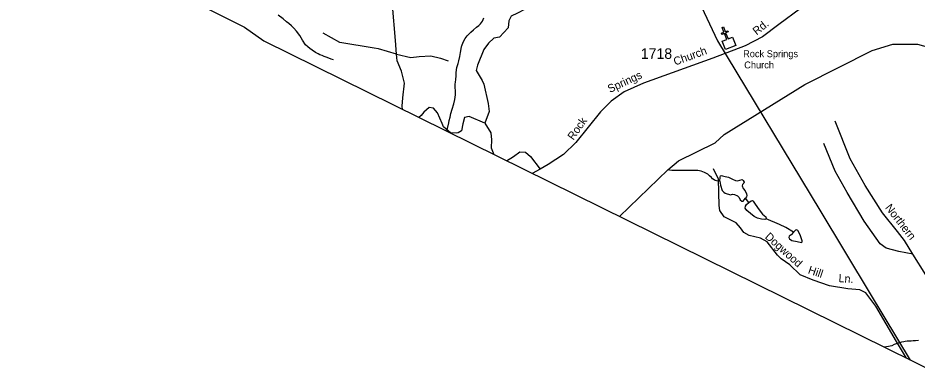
# Model space of a CAD drawing. Extents: x 2056842 to 2160602, y 826753 to 1016856.
# Drawn here: x 2099244 to 2109914, y 837921 to 842142 of the extents above; entities that cross this region are included whole.
import ezdxf

# ---------------------------------------------------------------- set-up
doc = ezdxf.new("R2010")
doc.units = 0
for name, color, linetype in [('Exist Boundary Political CountyLine', 7, 'Continuous'), ('Exist Cultural Church CELL', 7, 'Continuous'), ('Exist Cultural Church Label', 7, 'Continuous'), ('Exist Hydrographic Misc Water Feature', 7, 'Continuous'), ('Exist Road Non-System Type 51', 7, 'Continuous'), ('Exist Road Non-System Type 51 Label', 7, 'Continuous'), ('Exist Road Secondary Type 51 Attributed', 7, 'Continuous'), ('Exist Road Secondary Type 51 Label', 7, 'Continuous'), ('Exist Road Secondary Type 51 Number Label', 7, 'Continuous'), ('Exist Utilities Electrical Transmission Line', 7, 'Continuous')]:
    doc.layers.add(name, color=color, linetype=linetype)

msp = doc.modelspace()

# ---------------------------------------------------------------- linework, layer by layer
at = {"layer": 'Exist Boundary Political CountyLine'}
msp.add_lwpolyline([(2087202, 846842), (2088279, 846703), (2089061, 846621), (2089593, 846564), (2090401, 846476), (2091507, 846372), (2092417, 846284), (2093038, 846221), (2093614, 846163), (2094823, 845563), (2096040, 844956), (2096291, 844828), (2097736, 844110), (2098906, 843531), (2099955, 843015), (2100389, 842806), (2101933, 842033), (2102162, 841869), (2110170, 837921)], dxfattribs=at)
at = {"layer": 'Exist Cultural Church CELL'}
msp.add_lwpolyline([(2107603, 841867), (2107656, 841888), (2107628, 841959), (2107598, 841947), (2107593, 841962), (2107622, 841974), (2107601, 842030), (2107616, 842036), (2107637, 841980), (2107667, 841991), (2107673, 841976), (2107643, 841965), (2107671, 841894), (2107724, 841915), (2107763, 841815), (2107641, 841768)], close=True, dxfattribs=at)
at = {"layer": 'Exist Hydrographic Misc Water Feature'}
for points in [[(2102987, 841646), (2102963, 841654), (2102915, 841674), (2102879, 841686), (2102853, 841696), (2102827, 841706), (2102807, 841716), (2102777, 841734), (2102737, 841760), (2102709, 841781), (2102686, 841799), (2102656, 841825), (2102622, 841877), (2102590, 841933), (2102548, 841985), (2102518, 842021), (2102492, 842049), (2102458, 842078), (2102432, 842098), (2102390, 842130), (2102332, 842174)], [(2104333, 840799), (2104359, 840897), (2104363, 840928), (2104373, 840967), (2104381, 841009), (2104397, 841060), (2104415, 841125), (2104428, 841177), (2104436, 841231), (2104436, 841277), (2104434, 841319), (2104434, 841357), (2104438, 841379), (2104441, 841413), (2104445, 841455), (2104445, 841491), (2104447, 841529), (2104453, 841555), (2104467, 841601), (2104477, 841635), (2104487, 841685), (2104495, 841733), (2104502, 841777), (2104508, 841805), (2104511, 841813), (2104528, 841855), (2104550, 841897), (2104574, 841931), (2104618, 841973), (2104650, 842001), (2104686, 842032), (2104712, 842054), (2104734, 842074), (2104759, 842106), (2104773, 842144)], [(2106383, 839788), (2106958, 840341), (2107084, 840450), (2107517, 840661), (2107625, 840761), (2108581, 841355), (2109380, 841758), (2109629, 841832), (2109921, 841832), (2110305, 841726), (2110838, 841722), (2110920, 841729)], [(2107575, 840208), (2107533, 840213), (2107519, 840215), (2107505, 840222), (2107488, 840233), (2107473, 840250), (2107453, 840271), (2107433, 840289), (2107391, 840308), (2107352, 840324), (2107312, 840332), (2107248, 840334), (2107187, 840334), (2107156, 840334), (2107106, 840334), (2107004, 840335), (2106977, 840339), (2106958, 840341)], [(2107575, 840208), (2107576, 840254), (2107583, 840269), (2107595, 840274), (2107604, 840272), (2107636, 840264), (2107675, 840255), (2107726, 840232), (2107761, 840216), (2107782, 840213), (2107838, 840226), (2107852, 840216), (2107861, 840194), (2107857, 840182), (2107843, 840167), (2107840, 840151), (2107849, 840120), (2107873, 840091), (2107891, 840057), (2107895, 840038), (2107891, 840020), (2107878, 840004)], [(2107575, 840208), (2107582, 840161), (2107602, 840098), (2107621, 840075), (2107638, 840066), (2107702, 840044), (2107726, 840051), (2107747, 840049), (2107785, 840033), (2107803, 840015), (2107815, 839984), (2107834, 839970), (2107850, 839970), (2107864, 839984), (2107878, 840004)], [(2108125, 839759), (2108106, 839752), (2108070, 839756), (2108022, 839767), (2107982, 839788), (2107895, 839858), (2107876, 839887), (2107878, 839911), (2107892, 839930), (2107920, 839956)], [(2107920, 839956), (2107878, 840004)], [(2107920, 839956), (2107944, 839975), (2107963, 839977), (2107970, 839970), (2107994, 839935), (2108041, 839867), (2108080, 839817), (2108118, 839785), (2108124, 839769), (2108125, 839759)], [(2108448, 839602), (2108359, 839659), (2108283, 839693), (2108125, 839759)], [(2108448, 839602), (2108419, 839572), (2108396, 839554), (2108393, 839541), (2108399, 839524), (2108430, 839503), (2108493, 839492), (2108543, 839481), (2108552, 839488), (2108552, 839501), (2108528, 839572), (2108499, 839623), (2108485, 839631), (2108470, 839627), (2108448, 839602)], [(2109930, 838319), (2109898, 838316), (2109870, 838314), (2109844, 838312), (2109823, 838312), (2109798, 838310), (2109774, 838308), (2109758, 838304), (2109730, 838298), (2109692, 838288), (2109668, 838279), (2109642, 838270), (2109616, 838256), (2109597, 838249), (2109577, 838245), (2109523, 838240)]]:
    msp.add_lwpolyline(points, dxfattribs=at)
at = {"layer": 'Exist Road Non-System Type 51'}
for points in [[(2103735, 841713), (2103723, 841875), (2103689, 842295), (2103695, 842468), (2103734, 842599), (2103705, 842699), (2103628, 842709), (2103476, 842686), (2102936, 842705), (2102854, 842800), (2102728, 842893), (2102618, 842956), (2102566, 843062), (2102470, 843180), (2102343, 843340), (2102254, 843392), (2102194, 843450)], [(2105810, 842496), (2105731, 842521), (2105629, 842525), (2105523, 842515), (2105449, 842488), (2105376, 842438), (2105305, 842297), (2105264, 842245), (2105172, 842199), (2105098, 842162), (2105069, 842110), (2105060, 842026), (2104957, 841913), (2104893, 841903), (2104827, 841845), (2104773, 841770), (2104698, 841583), (2104683, 841518), (2104752, 841402), (2104773, 841358), (2104823, 841129), (2104838, 841035), (2104786, 840894)], [(2103735, 841713), (2103521, 841775), (2103473, 841783), (2103065, 841853), (2102866, 841961)], [(2103735, 841713), (2103906, 841672), (2104006, 841685), (2104143, 841695), (2104257, 841666), (2104350, 841634)], [(2103807, 841058), (2103804, 841097), (2103810, 841197), (2103831, 841368), (2103797, 841513), (2103743, 841634), (2103735, 841713)], [(2104376, 840780), (2104296, 840851), (2104279, 840890), (2104225, 841016), (2104175, 841072), (2104123, 841079), (2104059, 841025), (2104028, 840985), (2104003, 840961)], [(2104786, 840894), (2104599, 840973), (2104543, 840962), (2104524, 840885), (2104506, 840804), (2104469, 840780), (2104443, 840778), (2104376, 840780)], [(2109866, 839343), (2109766, 839502), (2109681, 839612), (2109506, 839831), (2109297, 840156), (2109119, 840472), (2108944, 840917)], [(2104786, 840894), (2104857, 840782), (2104863, 840696), (2104859, 840601), (2104893, 840522)], [(2109866, 839343), (2109697, 839373), (2109546, 839411), (2109477, 839465), (2109288, 839733), (2109085, 840073), (2108944, 840326), (2108809, 840653)], [(2105040, 840450), (2105127, 840499), (2105201, 840553), (2105268, 840549), (2105326, 840499), (2105440, 840348)], [(2109789, 838110), (2109669, 838308), (2109426, 838726), (2109307, 838885), (2109234, 838920), (2109093, 838931), (2108875, 838966), (2108681, 839032), (2108529, 839098), (2108404, 839214), (2108300, 839287), (2108257, 839331), (2108136, 839487), (2108055, 839530), (2107922, 839561), (2107859, 839600), (2107820, 839654), (2107768, 839712), (2107680, 839758), (2107626, 839783), (2107574, 839858), (2107566, 839920), (2107560, 840230), (2107500, 840352)], [(2110431, 838311), (2110357, 838470), (2110020, 839098), (2109866, 839343)]]:
    msp.add_lwpolyline(points, dxfattribs=at)
at = {"layer": 'Exist Road Secondary Type 51 Attributed'}
msp.add_lwpolyline([(2110385, 842772), (2109841, 842639), (2109107, 842457), (2108783, 842378), (2108654, 842320), (2108532, 842255), (2108275, 842063), (2108082, 841920), (2107876, 841812), (2107490, 841666), (2106666, 841370), (2106440, 841268), (2106286, 841156), (2106159, 841029), (2105863, 840665), (2105720, 840525), (2105535, 840403), (2105440, 840348), (2105347, 840298)], dxfattribs=at)
at = {"layer": 'Exist Utilities Electrical Transmission Line'}
msp.add_lwpolyline([(2090209, 878091), (2090400, 877911), (2091042, 877021), (2091167, 876876), (2095092, 871823), (2095202, 871659), (2098164, 867009), (2098185, 866905), (2098734, 864623), (2099023, 863476), (2099626, 861080), (2100400, 858057), (2100952, 855845), (2101981, 853662), (2102801, 851906), (2103297, 850945), (2103702, 850075), (2103841, 849731), (2105377, 846510), (2106244, 844637), (2107548, 841870), (2108761, 839865), (2109359, 838871), (2109834, 838086)], dxfattribs=at)

# ---------------------------------------------------------------- texts
at = {"layer": 'Exist Cultural Church Label'}
for s, height, p in [('Rock Springs', 82.02, (2107850, 841677)), ('Church', 82, (2107863, 841544))]:
    msp.add_text(s, height=height, dxfattribs=at).set_placement(p)
at = {"layer": 'Exist Road Non-System Type 51 Label'}
for s, rotation, p in [('Northern', 307.9081, (2109531, 839891)), ('Dogwood', 317.9914, (2108102, 839538)), ('Hill', 341.1292, (2108613, 839116)), ('Ln.', 356.1624, (2108981, 839011))]:
    msp.add_text(s, height=95, rotation=rotation, dxfattribs=at).set_placement(p)
at = {"layer": 'Exist Road Secondary Type 51 Label'}
for s, rotation, p in [('Rd.', 39.0445, (2108011, 841934)), ('Church', 19.9361, (2107044, 841577)), ('Springs', 24.9039, (2106269, 841252)), ('Rock', 54.822, (2105836, 840686))]:
    msp.add_text(s, height=95, rotation=rotation, dxfattribs=at).set_placement(p)
at = {"layer": 'Exist Road Secondary Type 51 Number Label'}
msp.add_text('1718', height=125, dxfattribs=at).set_placement((2106636, 841657))

doc.saveas('drawing.dxf')
